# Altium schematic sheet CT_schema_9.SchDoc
size 254 x 194 mm
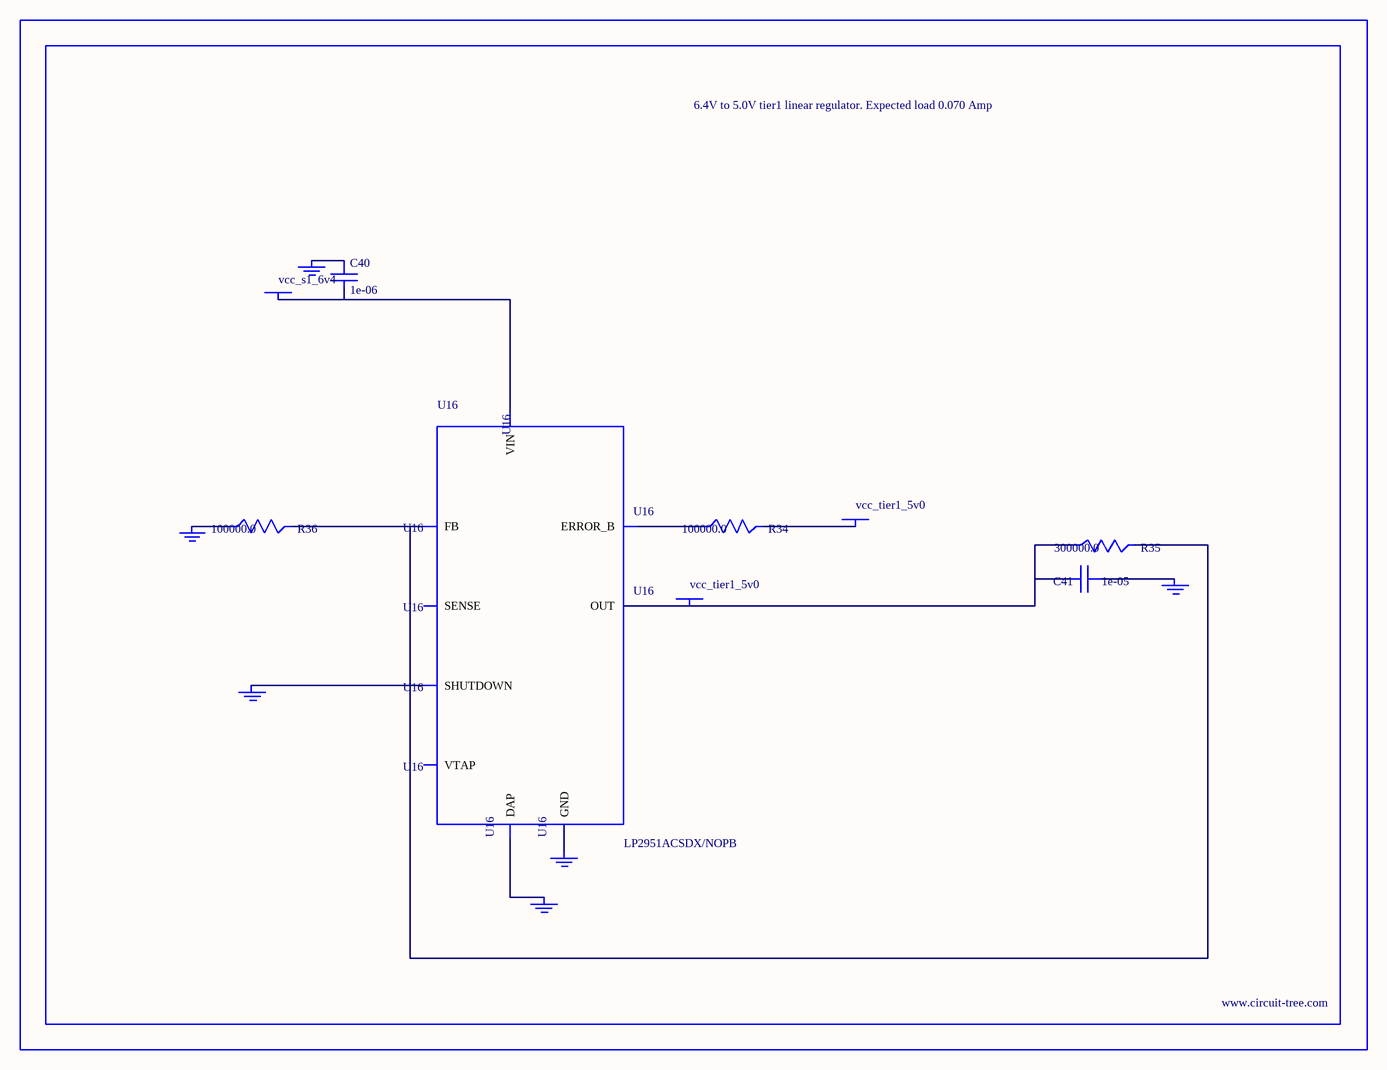
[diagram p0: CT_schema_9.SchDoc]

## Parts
BORDER8  (no value)
C40  1e-06  [C0603]
C41  1e-05  [C1210]
GND_INSTANCE_8_0  (no value)
GND_INSTANCE_8_1  (no value)
GND_INSTANCE_8_2  (no value)
GND_INSTANCE_8_3  (no value)
GND_INSTANCE_8_4  (no value)
GND_INSTANCE_8_5  (no value)
POWER_INSTANCE_8_0  vcc_tier1_5v0
POWER_INSTANCE_8_1  vcc_s1_6v4
POWER_INSTANCE_8_2  vcc_tier1_5v0
R34  100000.0  [R0603]
R35  300000.0  [R0603]
R36  100000.0  [R0603]
U16  LP2951ACSDX/NOPB  [WSON-8]

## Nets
NetC40_1: C40.1 GND_INSTANCE_8_3.0(GND)
NetC40_2: C40.2 POWER_INSTANCE_8_1.0(PWR) U16.8(VIN)
NetC41_1: C41.1 GND_INSTANCE_8_0.0(GND)
NetC41_2: C41.2 POWER_INSTANCE_8_2.0(PWR) R35.1 U16.1(OUT)
NetGND_INSTANCE_8_1_0: GND_INSTANCE_8_1.0(GND) U16.3(SHUTDOWN)
NetGND_INSTANCE_8_2_0: GND_INSTANCE_8_2.0(GND) R36.1
NetGND_INSTANCE_8_4_0: GND_INSTANCE_8_4.0(GND) U16.PAD(DAP)
NetGND_INSTANCE_8_5_0: GND_INSTANCE_8_5.0(GND) U16.4(GND)
NetPOWER_INSTANCE_8_0_0: POWER_INSTANCE_8_0.0(PWR) R34.2
NetR34_1: R34.1 U16.5(ERROR_B)
NetR35_2: R35.2 R36.2 U16.7(FB)

Not connected (* = marked no-connect by the designer): U16 2(SENSE) 6(VTAP)

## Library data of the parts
BORDER8 = BORDER_PAGE8
C40 = C0603C105K3RACTU
C41 = GRM32DR61E106MA12L
GND_INSTANCE_8_0-GND_INSTANCE_8_5 = GND
POWER_INSTANCE_8_0-POWER_INSTANCE_8_2 = PWR
R34 R36 = RC0603JR-07100KL
R35 = RC0603JR-07300KL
